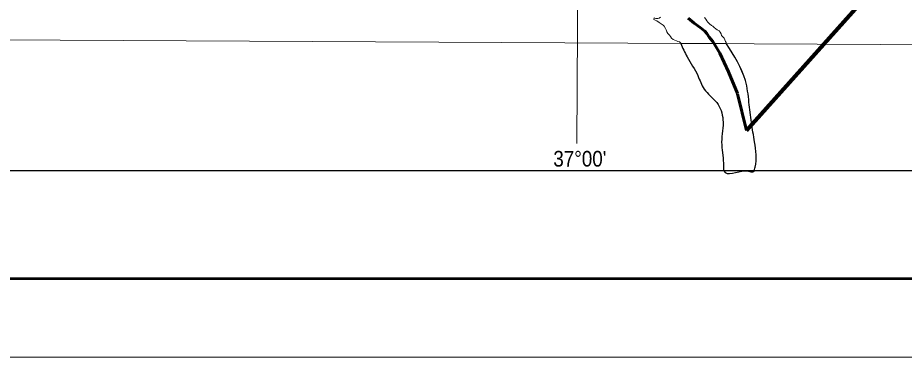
# Model space of a CAD drawing. Extents: x 553962 to 842807, y 8883888 to 9032388.
# Drawn here: x 701363 to 729677, y 8883888 to 8894722 of the extents above; entities that cross this region are included whole.
import ezdxf
from ezdxf.enums import TextEntityAlignment as Align

# ---------------------------------------------------------------- set-up
doc = ezdxf.new("R2010")
doc.units = 0
doc.header["$LTSCALE"] = 200
doc.linetypes.add('LONG_DASH_SHORT_DASH', pattern=[9.9, 6, -1.2, 1.5, -1.2])
for name, color, linetype, lineweight in [('1', 7, 'Continuous', 13), ('25', 7, 'Continuous', 13), ('3', 7, 'Continuous', 13), ('7', 7, 'LONG_DASH_SHORT_DASH', 60), ('9', 7, 'Continuous', 90)]:
    doc.layers.add(name, color=color, linetype=linetype, lineweight=lineweight)
doc.layers.add('46', color=7, linetype='Continuous')

msp = doc.modelspace()

# ---------------------------------------------------------------- linework, layer by layer
at = {"layer": '1'}
for points in [[(719978.9, 9023574.5), (719561.6, 8949232.2), (719215.6, 8890710.6)], [(564751.7, 8894587.5), (664411.9, 8894209.9), (791388.5, 8893536.2)]]:
    msp.add_lwpolyline(points, dxfattribs=at)
at = {"layer": '25', "lineweight": 25}
msp.add_line((724002.8, 8893886.5), (722537.3, 8893896.5), dxfattribs=at)
msp.add_line((724002.8, 8893886.5), (722537.3, 8893896.5), dxfattribs=at)
at = {"layer": '25'}
for points in [[(722073.4, 8894336.8), (722053.4, 8894382.8), (722013.2, 8894449.3), (721972.7, 8894485.2), (721917.1, 8894531.4), (721846.2, 8894572.6), (721770.2, 8894618.9), (721724.6, 8894639.6), (721673.9, 8894665.4), (721689.5, 8894716.2), (721745.3, 8894700.6), (721801.3, 8894700.2), (721852.2, 8894705), (721893.1, 8894740.4)], [(723301.9, 8894726.3), (723337.1, 8894675.1), (723367.3, 8894624), (723402.6, 8894583), (723453.1, 8894526.7), (723518.8, 8894475.3), (723564.4, 8894449.5), (723609.9, 8894408.5), (723655.5, 8894372.5), (723706.1, 8894336.6), (723761.8, 8894305.6), (723797.1, 8894259.6), (723827.3, 8894208.4), (723842.2, 8894157.4), (723887.6, 8894111.3), (723928.1, 8894075.3), (723948, 8894019.2)], [(722537.3, 8893896.5), (722543.5, 8893916.1), (722503.1, 8893952.1), (722447.2, 8893962.6), (722401.6, 8893983.3), (722350.9, 8894004), (722295.1, 8894024.7), (722244.5, 8894065.8), (722214.3, 8894122), (722174, 8894168.1), (722128.6, 8894224.4), (722098.4, 8894270.5), (722073.4, 8894336.8)], [(723948, 8894019.2), (723962.9, 8893968.2), (723993.2, 8893927.2), (724002.8, 8893886.5), (722537.3, 8893896.5)]]:
    msp.add_lwpolyline(points, dxfattribs=at)
at = {"layer": '25', "lineweight": 25}
for points in [[(722537.3, 8893896.5), (722740.6, 8893475.5), (723084.4, 8892873.8), (723285, 8892444), (723686.1, 8892014.3), (723886.7, 8891469.9), (723843.7, 8890753.6), (723901, 8890080.3), (723900.8, 8889934.8), (723915.3, 8889836.7), (724574.3, 8889836.7), (724631.6, 8889836.7), (724883.2, 8889836.5), (724893.2, 8889883.7), (724911.8, 8889958.1), (724898, 8890758.3), (724794.3, 8891380.3), (724717.6, 8892028.6), (724603, 8892716.2), (724002.8, 8893886.5)], [(722537.3, 8893896.5), (722740.6, 8893475.5), (723084.4, 8892873.8), (723285, 8892444), (723686.1, 8892014.3), (723886.7, 8891469.9), (723843.7, 8890753.6), (723901, 8890080.3), (723901.3, 8889998.4)], [(724811.6, 8891262.3), (724794.3, 8891380.3), (724717.6, 8892028.6), (724603, 8892716.2), (724002.8, 8893886.5)]]:
    msp.add_spline(points, degree=3, dxfattribs=at)
at = {"layer": '3'}
msp.add_lwpolyline([(842807.3, 9032387.8), (842807.3, 8883887.8), (553961.7, 8883887.8), (553961.7, 9032387.8)], close=True, dxfattribs=at)
msp.add_lwpolyline([(842807.3, 9032387.8), (842807.3, 8883887.8), (553961.7, 8883887.8), (553961.7, 9032387.8)], close=True, dxfattribs=at)
at = {"layer": '3', "lineweight": 53}
msp.add_lwpolyline([(840307.3, 9029887.8), (840307.3, 8886387.8), (560211.7, 8886387.8), (560211.7, 9029887.8)], close=True, dxfattribs=at)
msp.add_lwpolyline([(840307.3, 9029887.8), (840307.3, 8886387.8), (560211.7, 8886387.8), (560211.7, 9029887.8)], close=True, dxfattribs=at)
at = {"layer": '3', "lineweight": 25}
msp.add_lwpolyline([(563033.9, 9026438.8), (793061.1, 9026438.8), (793495.6, 8889836.8), (563468.3, 8889836.8)], close=True, dxfattribs=at)
msp.add_lwpolyline([(563033.9, 9026438.8), (793061.1, 9026438.8), (793495.6, 8889836.8), (563468.3, 8889836.8)], close=True, dxfattribs=at)
at = {"layer": '7'}
msp.add_lwpolyline([(724638.9, 8891123.6), (724349.6, 8892305.9), (724059.6, 8892992.2), (723788.9, 8893591.5), (723566.6, 8893968.5), (723450.6, 8894103.8), (723373.3, 8894219.2), (723307.3, 8894290.7), (723154.9, 8894408.1), (722972, 8894546), (722773.8, 8894710.7)], dxfattribs=at)
at = {"layer": '9'}
msp.add_lwpolyline([(724638.9, 8891123.6), (729122.2, 8896139.1), (740717.5, 8896813.6), (741371.9, 8898310.2)], dxfattribs=at)

# ---------------------------------------------------------------- texts
at = {"layer": '46', "width": 0.9}
msp.add_text("37°00'", height=500, dxfattribs=at).set_placement((719315, 8889973.1), align=Align.CENTER)

doc.saveas('drawing.dxf')
